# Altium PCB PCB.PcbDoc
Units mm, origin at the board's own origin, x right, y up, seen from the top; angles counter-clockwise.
Board outline 41 x 25.36 mm, 2 copper layers (TOP, BOTTOM), stack 1.586 mm thick; 36 components, 21 nets, 107 pads, 50 vias.
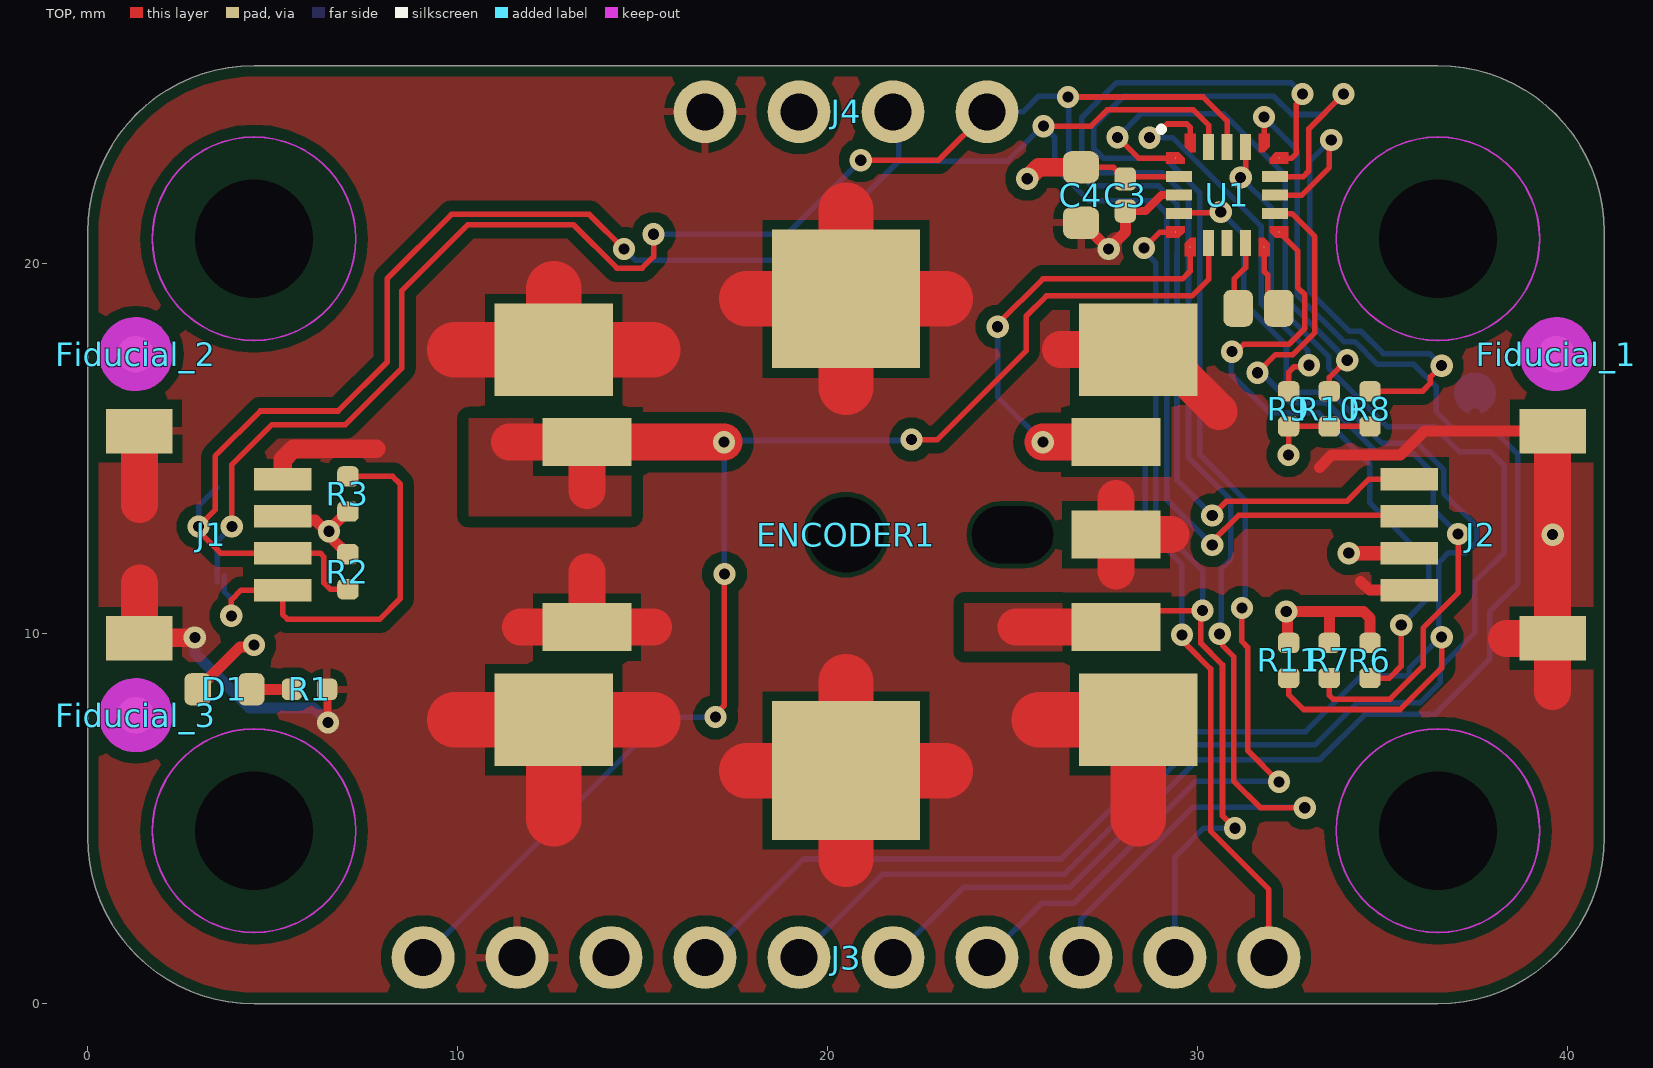
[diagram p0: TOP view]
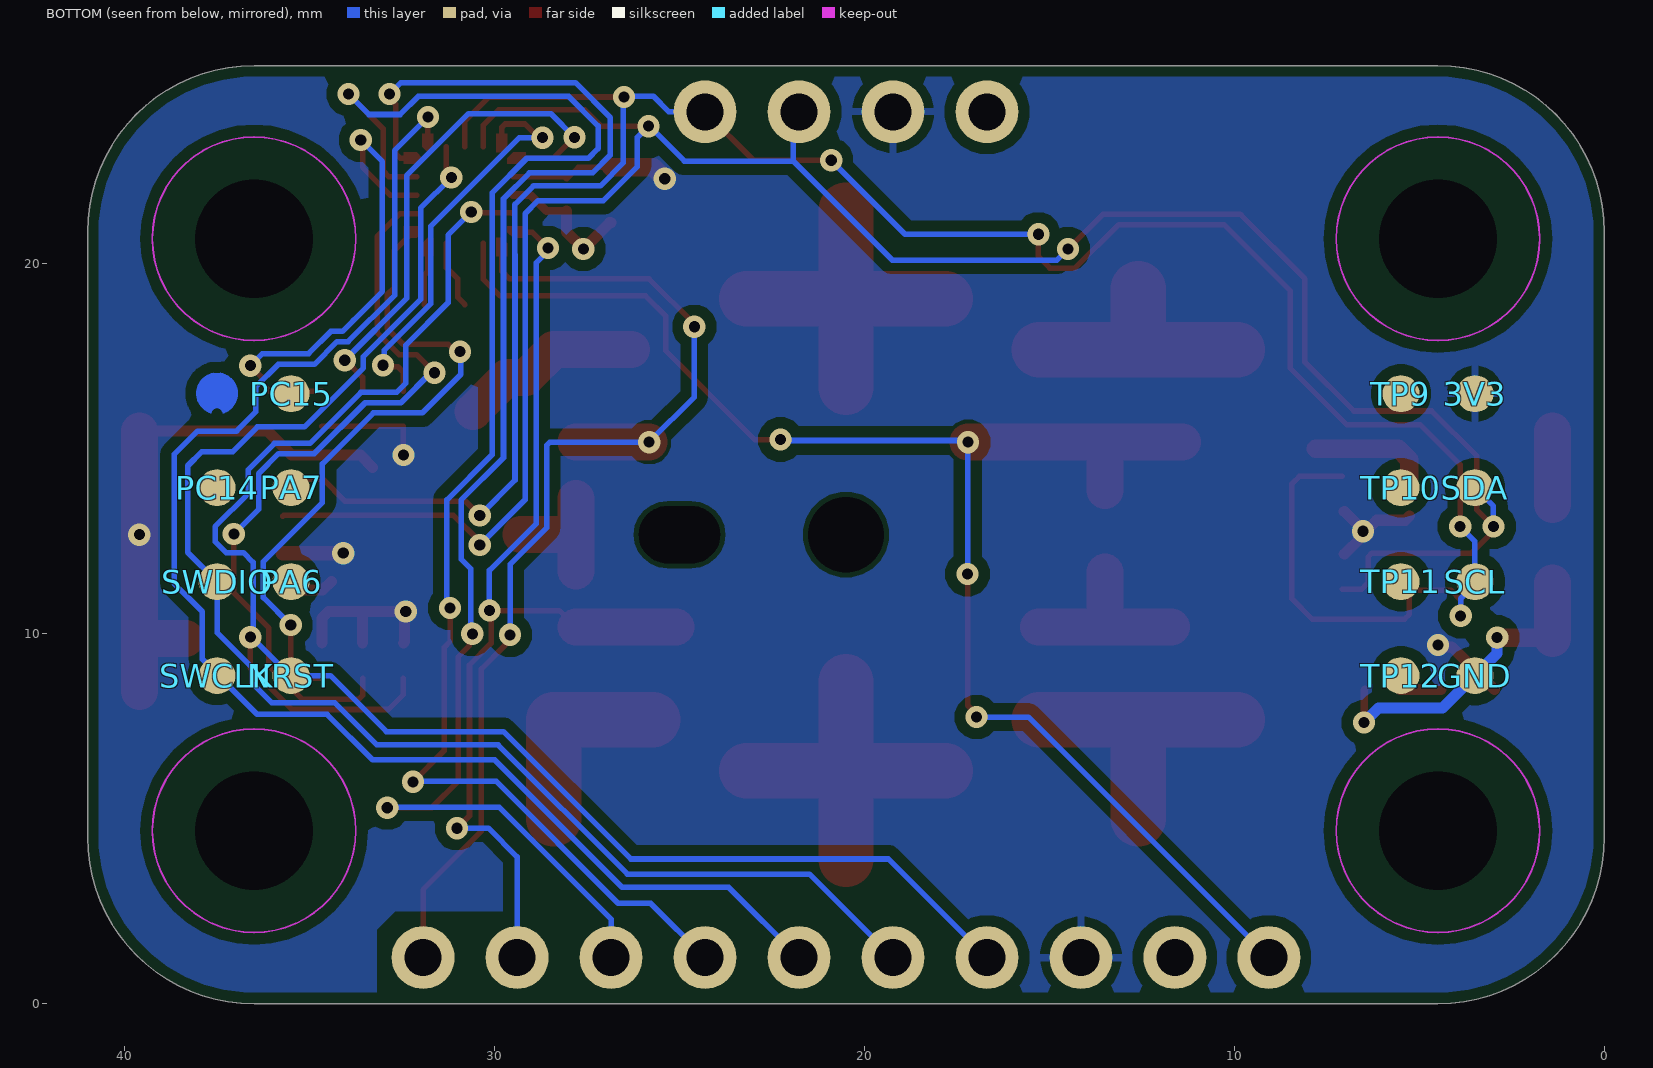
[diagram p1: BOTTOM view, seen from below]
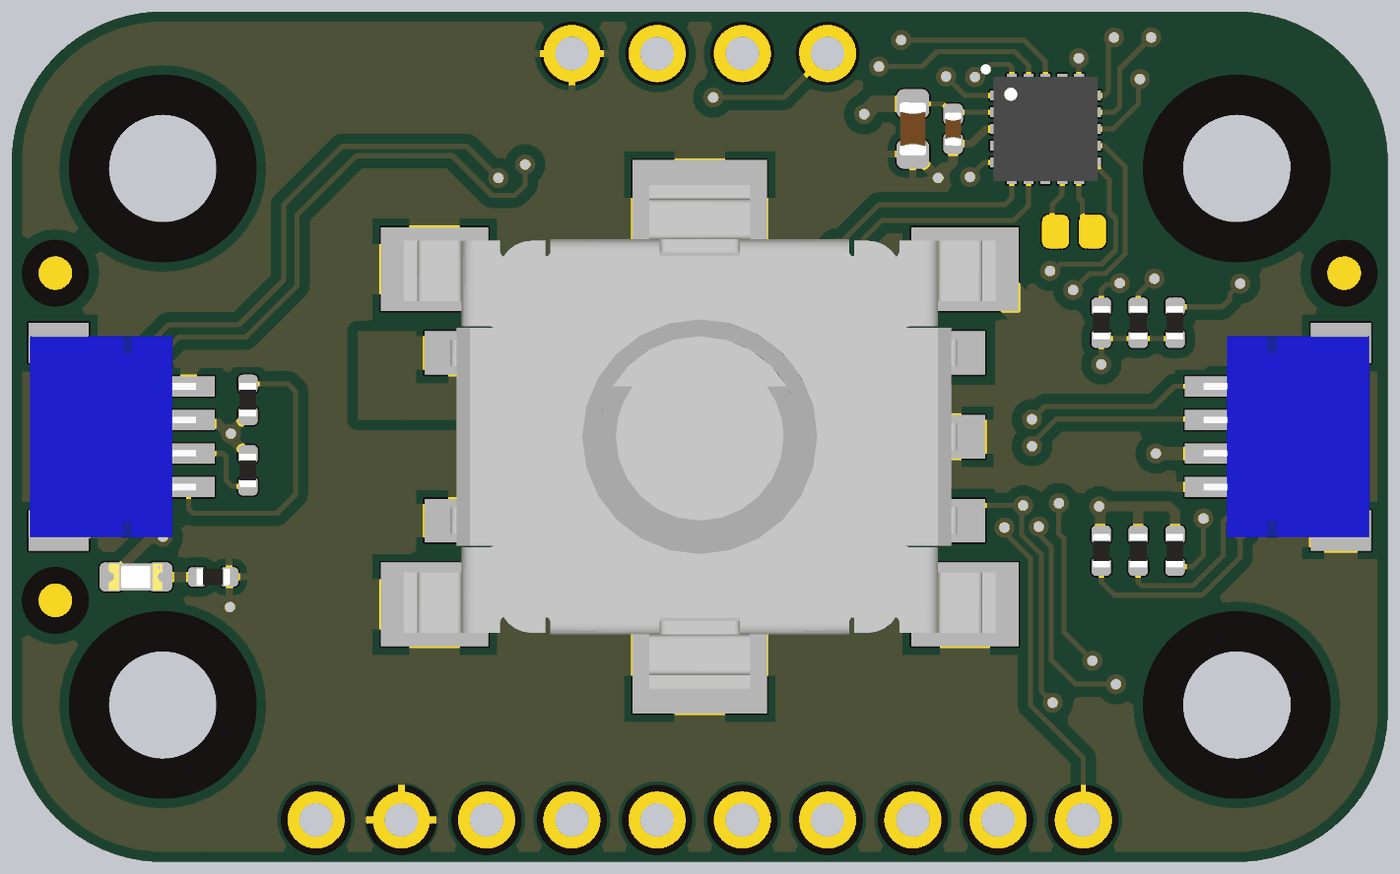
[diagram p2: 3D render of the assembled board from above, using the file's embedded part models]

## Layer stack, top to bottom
Top Solder: solder mask 0.01, Solder Resist, Dk 3.5
TOP: signal copper 0.018
Dielectric: core 1.55, FR-4, Dk 4.8
BOTTOM: signal copper 0.018
Bottom Solder: solder mask 0.01, Solder Resist, Dk 3.5

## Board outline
0,4.5 ccw(c4.5,4.5) 4.5,0 36.5,0 ccw(c36.5,4.5) 41,4.5 41,20.86 ccw(c36.5,20.86) 36.5,25.36 4.5,25.36 ccw(c4.5,20.86) 0,20.86

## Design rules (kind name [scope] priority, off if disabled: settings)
BoardOutlineClearance Version [(ObjectKind = 'Text') And (StringText = '.Version')] p1: gap=0 ignorepadtopadclearanceinfootprint=FALSE
BoardOutlineClearance Mousebites [(ObjectKind = 'Pad') And (Name = 'Free-MOUSEBITE')] p2: gap=0 ignorepadtopadclearanceinfootprint=FALSE
BoardOutlineClearance Silks [(OnLayer('Top Overlay') OR OnLayer('Bottom Overlay'))] p3: gap=0 ignorepadtopadclearanceinfootprint=FALSE
BoardOutlineClearance [All] p4: gap=0.3 ignorepadtopadclearanceinfootprint=FALSE
Clearance COPPER_0.3mm [All] p1: gap=0.127 ignorepadtopadclearanceinfootprint=FALSE except(0.3: Arc-Fill Arc-Poly Arc-Region Track-Fill Track-Poly Track-Region SMDPad-Fill SMDPad-Poly SMDPad-Region THPad-Fill THPad-Poly THPad-Region Via-Fill Via-Poly Via-Region Fill-Fill Fill-Poly Fill-Region Poly-Poly Poly-Region Region-Region)
Clearance "Generic clearance 0.15mm" [All] p2: gap=0.15 ignorepadtopadclearanceinfootprint=FALSE
ComponentClearance [All] p1: gap=0.2 collisioncheckmode=3 verticalgap=0 showdistances=TRUE
DiffPairsRouting USB [InDifferentialPairClass('USB')] p1: maxlimit=0.15 minlimit=0.15 mostfreqgap=0.15 toplayer_minwidth=0.15 toplayer_maxwidth=0.21 toplayer_prefwidth=0.2 bottomlayer_minwidth=0.15 bottomlayer_maxwidth=0.21 bottomlayer_prefwidth=0.2 impedanceprofiledriven=TRUE impedanceprofileid={E6B00C31-4C8E-439C-824F-D2B2CDC26F9C} impedanceprofilevalue=90.000000 maxuncoupledlength=12.7
Height [All] p1: minheight=0 maxheight=30 prefheight=12.7
HoleSize [All] p1: absolutevalues=TRUE maxlimit=30 minlimit=0.3 maxpercent=80.000 minpercent=20.000
HoleToHoleClearance [All] p1: gap=0.25 allowstackedmicrovias=FALSE
MinimumAnnularRing [All] p1: minimumring=0.15
PlaneConnect [All] p1: pad.planeconnectstyle=Relief pad.reliefexpansion=0.508 pad.reliefentries=4 pad.reliefconductorwidth=0.254 pad.reliefairgap=0.254 via.planeconnectstyle=Direct via.reliefexpansion=0.508 via.reliefentries=4 via.reliefconductorwidth=0.254 via.reliefairgap=0.254
PolygonConnect [All] p1: thpad.connectstyle=Relief thpad.reliefconductorwidth=0.2 thpad.reliefentries=4 thpad.polygonreliefangle="90 Angle" thpad.airgapwidth=0.254 smdpad.connectstyle=Relief smdpad.reliefconductorwidth=0.2 smdpad.reliefentries=4 smdpad.polygonreliefangle="90 Angle" smdpad.airgapwidth=0.254 via.connectstyle=Direct via.reliefconductorwidth=0.254 via.reliefentries=4 via.polygonreliefangle="90 Angle" via.airgapwidth=0.254
RoomDefinition TOP [InComponentClass('TOP')] p1: confinementstyle=ConfineIn formatcopy=TRUE lockcomponents=FALSE outline 42.8,3.6 51.5,3.6 51.5,18.3 42.8,18.3
RoutingVias StandardVias [All] p1: holewidth=0.3 width=0.6 viastyle="Through Hole" minholewidth=0.3 minwidth=0.6 maxholewidth=0.3 maxwidth=0.6
SMDToCorner [All] p1: distance=39370
SilkToSilkClearance [All] p1: silktosilkclearance=0.2
SilkToSolderMaskClearance [IsPad] p1: minsilkscreentomaskgap=0.15 clearancetoexposedcopper=TRUE
SolderMaskExpansion VIAtented [IsVia] p1: expansion=0.102 istentingtop=TRUE
SolderMaskExpansion [All] p2: expansion=0.05 istentingtop=FALSE
UnConnectedPin [All] p1:
UnRoutedNet [not WithinRoom('K36')] p1: checkbadconnections=TRUE
ViasUnderSMD [All] p1: allowed=FALSE
Width StandardTraces [All] p1: maxlimit=5 minlimit=0.15 preferedwidth=0.15 minimp=50.000000 maximp=50.000000 favimp=50.000000
21 further rules are at their usual default settings.

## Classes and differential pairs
component class TOP: 3V3 D1 ENCODER1 Fiducial_1 Fiducial_2 Fiducial_3 GND J1 J2 J3 J4 NRST PA6 PA7 PC14 PC15 R1 SCL SDA SWCLK SWDIO TP9 TP10 TP11 TP12
component class U_MICROCONTROLLER: C3 C4 R2 R3 R6 R7 R8 R9 R10 R11 U1

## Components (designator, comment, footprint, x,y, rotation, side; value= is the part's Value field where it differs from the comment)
3V3 "Test point 1.00mm" TP-1.00MM 3.5,16.49 r90 bottom
C3 "0402B104K160CT" CAP-0402 28.05,21.86 r270 top value=100nF
C4 "GRM188R61C475KAAJD" CAP-0603 26.85,21.86 r90 top value=4.7µF
D1 "HSMG-C190" LEDC1608X80N-AK 3.7,8.5 r180 top
ENCODER1 "PEC11J-9215F-S0015" PEC11J-9215F-S0015 20.5,12.68 r90 top
Fiducial_1 "Fiducial mark 1mm" "Fiducial mark 1mm-Footprint-1" 39.7,17.56 r270 top
Fiducial_2 "Fiducial mark 1mm" "Fiducial mark 1mm-Footprint-1" 1.3,17.56 r270 top
Fiducial_3 "Fiducial mark 1mm" "Fiducial mark 1mm-Footprint-1" 1.3,7.8 r270 top
GND "Test point 1.00mm" TP-1.00MM 3.5,8.87 r90 bottom
J1 "SM04B-SRSS-TB(LF)(SN)" SM04B-SRSS-TB(LF)(SN)-Footprint-1 3.337,12.68 r90 top locked
J2 "SM04B-SRSS-TB(LF)(SN)" SM04B-SRSS-TB(LF)(SN)-Footprint-1 37.663,12.68 r270 top locked
J3 "HEADER TH 2.54mm VERT. 1x010POS" "PIN HEADER 2.54mm VERT. 1x10POS" 20.5,1.25 r0 top
J4 "HEADER TH 2.54mm VERT. 1x004POS" "PIN HEADER 2.54mm VERT. 1x4POS-Footprint-1" 20.5,24.11 r0 top
NRST "Test point 1.00mm" TP-1.00MM 35.5,8.87 r180 bottom
PA6 "Test point 1.00mm" TP-1.00MM 35.5,11.41 r180 bottom
PA7 "Test point 1.00mm" TP-1.00MM 35.5,13.95 r180 bottom
PC14 "Test point 1.00mm" TP-1.00MM 37.5,13.95 r180 bottom
PC15 "Test point 1.00mm" TP-1.00MM 35.5,16.49 r180 bottom
R1 "CRCW04021K00FKEDC" RES-0402 6,8.5 r180 top value=1k
R2 "RC0402FR-074K7L" RES-0402 7.039,11.68 r90 top value=4.7k
R3 "RC0402FR-074K7L" RES-0402 7.039,13.78 r270 top value=4.7k
R6 "RC0402FR-074K7L" RES-0402 34.663,9.28 r270 top value=4.7k
R7 "RC0402FR-074K7L" RES-0402 33.563,9.28 r270 top value=4.7k
R8 "RC0402FR-074K7L" RES-0402 34.663,16.08 r90 top value=4.7k
R9 "RC0402FR-074K7L" RES-0402 32.463,16.08 r90 top value=4.7k
R10 "RC0402FR-074K7L" RES-0402 33.563,16.08 r90 top value=4.7k
R11 "RC0402FR-074K7L" RES-0402 32.463,9.28 r270 top value=4.7k
SCL "Test point 1.00mm" TP-1.00MM 3.5,11.41 r90 bottom
SDA "Test point 1.00mm" TP-1.00MM 3.5,13.95 r90 bottom
SWCLK "Test point 1.00mm" TP-1.00MM 37.5,8.87 r180 bottom
SWDIO "Test point 1.00mm" TP-1.00MM 37.5,11.41 r180 bottom
TP9 "Test point 1.00mm" TP-1.00MM 5.5,16.49 r0 bottom
TP10 "Test point 1.00mm" TP-1.00MM 5.5,13.95 r0 bottom
TP11 "Test point 1.00mm" TP-1.00MM 5.5,11.41 r0 bottom
TP12 "Test point 1.00mm" TP-1.00MM 5.5,8.87 r0 bottom
U1 "STM32C011F4U6TR" UFQFPN20 30.8,21.86 r0 top

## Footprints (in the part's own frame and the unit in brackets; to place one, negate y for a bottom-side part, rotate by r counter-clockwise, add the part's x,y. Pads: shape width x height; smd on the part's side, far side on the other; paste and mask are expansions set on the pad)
CAP-0402 [mm] "Chip Capacitor, 2-Leads, Body  0402 (in) 1005 (mm), IPC Medium Density"
  rrect52% 0.63x0.58 smd mask+0.05: 1(-0.435,0) 2(0.435,0)
  body extent -0.5,-0.25 0.5,0.25, height 0.5
CAP-0603 [mm] "Chip Capacitor, Body 0603 imperial,1.6x0.8mm, IPC High Density"
  rrect51% 0.87x0.97 smd mask+0.05: 1(-0.75,0) 2(0.75,0)
  body extent -0.8,-0.4 0.8,0.4, height 0.8
"Fiducial mark 1mm-Footprint-1" [mm]
  round 1 smd paste-10 mask+0.5: 1(0,0)
  TOP keep-out circle w1: c0,0 r0.5
LEDC1608X80N-AK [mm]
  rrect50% 0.72x0.87 smd: A(0.725,0) C(-0.725,0)
  body extent -0.8,-0.4 0.8,0.4, height 0.79
PEC11J-9215F-S0015 [mm]
  rect 1.3x2.4 smd: A(-2.5,-7.3) B(2.5,-7.3) C(0,-7.3) D(-2.5,7) E(2.5,7)
  rect 3.75x4 smd: FIXING(-6.375,0) FIXING(6.375,0)
  rect 2.5x3.2 smd: FIXING(-5,7.9) FIXING(-5,-7.9) FIXING(5,7.9) FIXING(5,-7.9)
  round 0.5 hole 2.05 unplated: PLASTIC(0,0)
  round 0.5 hole 1.55 slot 2.2 at 90 deg unplated: PLASTIC(0,-4.5)
  body extent -7.51,-8.82 7.51,8.82, height 19.52
"PIN HEADER 2.54mm VERT. 1x4POS-Footprint-1" [mm]
  round 1.7 hole 1 mask+0.1: 1(-3.81,0) 2(-1.27,0) 3(1.27,0) 4(3.81,0)
"PIN HEADER 2.54mm VERT. 1x10POS" [mm]
  round 1.7 hole 1 mask+0.2: 1(-11.43,0) 2(-8.89,0) 3(-6.35,0) 4(-3.81,0) 5(-1.27,0) 6(1.27,0) 7(3.81,0) 8(6.35,0) 9(8.89,0) 10(11.43,0)
RES-0402 [mm] "Chip Resistor, 2-Leads, Body  0402 (in) 1005 (mm), IPC Medium Density"
  rrect51% 0.55x0.58 smd mask+0.05: 1(-0.475,0) 2(0.475,0)
  body extent -0.5,-0.25 0.5,0.25, height 0.34
SM04B-SRSS-TB(LF)(SN)-Footprint-1 [mm]
  rect 0.6x1.55 smd mask+0.05: 1(1.5,-1.937) 2(0.5,-1.937) 3(-0.5,-1.937) 4(-1.5,-1.937)
  rect 1.2x1.8 smd mask+0.05: FIX(-2.8,1.938) FIX(2.8,1.938)
  body extent -3,-2.16 3,2.8, height 2.98
TP-1.00MM [mm]
  rrect100% 1x1 smd paste-2.54: X(0,0)
UFQFPN20 [mm] "QFN, 20-Leads, Body 3.00x3.00mm, Pitch 0.50mm, IPC Medium Density"
  round 0.025 smd mask+0.05: 1(-1.4,1) 5(-1.4,-1) 6(-1,-1.4) 10(1,-1.4) 11(1.4,-1) 15(1.4,1) 16(1,1.4) 20(-1,1.4)
  rect 0.7x0.3 smd mask+0.05: 2(-1.3,0.5) 3(-1.3,0) 4(-1.3,-0.5) 12(1.3,-0.5) 13(1.3,0) 14(1.3,0.5)
  rect 0.3x0.7 smd mask+0.05: 7(-0.5,-1.3) 8(0,-1.3) 9(0.5,-1.3) 17(0.5,1.3) 18(0,1.3) 19(-0.5,1.3)
  TOP region: -1.3,-1.15 -1.15,-1 -1.15,-0.85 -1.65,-0.85 -1.65,-1.15
  TOP region: -0.85,-1.65 -1.15,-1.65 -1.15,-1.3 -1,-1.15 -0.85,-1.15
  TOP region: 1.15,-1.65 0.85,-1.65 0.85,-1.15 1,-1.15 1.15,-1.3
  TOP region: 1.65,1.15 1.65,0.85 1.15,0.85 1.15,1 1.3,1.15
  TOP region: 1,1.15 0.85,1.15 0.85,1.65 1.15,1.65 1.15,1.3
  TOP region: -1.15,1 -1.15,0.85 -1.65,0.85 -1.65,1.15 -1.3,1.15
  TOP region: -1.15,1.3 -1,1.15 -0.85,1.15 -0.85,1.65 -1.15,1.65
  TOP region: 1.65,-0.85 1.65,-1.15 1.3,-1.15 1.15,-1 1.15,-0.85
  silkscreen extent -1.8,1.75 -1.75,1.8, body extent -1.55,-1.55 1.55,1.55, height 0.6

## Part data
3V3 GND NRST PA6 PA7 PC14 PC15 SCL SDA SWCLK SWDIO TP9 TP10 TP11 TP12: library part UT0013-A.6, Manufacturer="This is not a component"
C3: library part C0012-A.15, "CAP CHIP 0402 100nF 10% 16V X7R", Case Code (Imperial)=0402, Dielectric=X7R, Manufacturer=Walsin, Tolerance=10%, Voltage=16V
C4: library part C0054-A.16, "CAP CHIP 0603 4.7uF 10% 16V X5R", Case Code (Imperial)=0603, Dielectric=X5R, Manufacturer=Murata, Manufacturer 3="Samsung Electro-Mechanics", Part number 2=GRM188R61C475KE11D, Part number 3=CL10A475KO8NNNC, Tolerance=10%, Voltage=16V
D1: library part L0009-A.5, "LED SMD 0603 GREEN/568 15mcd 120^", Manufacturer=Broadcom
ENCODER1: library part S0054-A.2, "ENCODER 2b quadrature, 15PPR, 30 detents, shaft 15mm D-Cut, switch 350+-100gf, SMD 15x18x20mm", Manufacturer=Bourns
Fiducial_1 Fiducial_2 Fiducial_3: library part UT0023-A.7, "Fiducial mark 1mm clearance 2mm"
J1 J2: library part J0005-A.2, "CONN JST 4POS SIDE 1MM TIN QWIIC", Manufacturer=JST
J3: library part J0169-A.8
J4: library part J0162-A.5
R1: library part R0007-A.24, "RES CHIP 0402 1k 1% 1/16W", Case Code (Imperial)=0402, Manufacturer=Vishay, Power=62.5mW, Temperature Coefficient=100ppm, Tolerance=1%
R2 R3 R6 R7 R8 R9 R10 R11: library part R0013-A.24, "RES CHIP 0402 4k7 1% 1/16W", Case Code (Imperial)=0402, Manufacturer=YAGEO, Power=62.5mW, Temperature Coefficient=200ppm, Tolerance=1%
U1: library part U0363-A.3, "IC Cortex M0, 32b MCU, 32KB Flash, 6KB RAM, VDD 2-3.6V, -40°C to 85°C, QFN20 3x3mm", Manufacturer="ST Microelectronics"

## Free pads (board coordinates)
  rrect50% 0.8x1 smd paste-2539.97: 3V10(31.1,18.8) 3V10(32.2,18.8)
  round 3 hole 3.2 unplated paste-2539.97 mask+1.3: MH(4.5,4.68) MH(4.5,20.68) MH(36.5,4.68) MH(36.5,20.68)

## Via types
v1: diameter 0.6, hole 0.3, TOP to BOTTOM, tented both sides, 50 vias

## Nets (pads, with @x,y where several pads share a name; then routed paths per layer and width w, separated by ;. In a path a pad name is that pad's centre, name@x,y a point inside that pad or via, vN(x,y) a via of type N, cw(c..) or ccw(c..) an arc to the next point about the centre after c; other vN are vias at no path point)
+3V3: 3V3.X C3.1 C4.2 D1.A J1.2 J2.2 J3.3 J4.2 R2.2 R3.2 R6.1 R7.1 R8.1 R9.1 R10.1 R11.1 U1.2 | length 18.8
  TOP w0.15: C4.2 27.735,22.61 C3.1 28.115,22.36 U1.2 ; v1(32.463,14.837) R9.1 R10.1 R8.1
  TOP w0.3: D1.A 4.118,9.643 4.443,9.643 v1(4.5,9.7) ; J1.2 5.384,13.07 6.154,13.07 6.453,12.772 v1(6.53,12.772) ; R2.2 7.024,12.155 6.587,12.592 6.587,12.714 v1(6.53,12.772) ; R3.2 7.024,13.305 6.608,12.889 6.608,12.85 v1(6.53,12.772) ; R11.1 32.432,9.787 32.432,10.568 v1(32.4,10.6) 34.487,10.6 34.663,10.424 R6.1 ; 33.514,10.6 33.563,10.551 R7.1
  TOP w0.4: v1(34.088,12.18) J2.2
  TOP w0.5: v1(25.4,22.3) 25.71,22.61 C4.2
GND: C3.2 C4.1 ENCODER1.C ENCODER1.D ENCODER1.FIXING GND.X J1.1 J1.FIX J2.1 J2.FIX J3.2 J4.1 R1.1 U1.3 | length 88.4
  TOP w0.2: R1.1 6.488,8.488 6.488,7.612 v1(6.5,7.6)
  TOP w0.22: C3.2 28.592,21.425 29.027,21.86 U1.3
  TOP w0.3: C4.1 26.895,21.11 v1@27.6,20.405 ; v1(27.6,20.4) v1@27.6,20.405 ; C3.2 28.05,20.866 27.6,20.416 v1@27.6,20.405 ; 33.3,14.5 33.628,14.828 35.486,14.828 36.138,15.48 J2.FIX@39.601,15.48 ; 34.406,11.419 34.645,11.18 J2.1
  TOP w0.5: J1.FIX@1.399,9.88 1.419,9.9 v1(2.9,9.9) ; J1.1 5.275,14.707 5.567,15 7.8,15
  TOP w1: J1.FIX@1.399,9.88 1.399,11.379 ; 1.399,13.499 J1.FIX@1.399,15.48 ; 11.7,10.18 ENCODER1.D ; 13.5,11.671 ENCODER1.D ; 15.3,10.18 ENCODER1.D ; 26.3,17.68 28.4,17.68 29.15,16.93 29.661,16.93 30.581,16.01 ; 27.8,11.7 ENCODER1.C ; 27.8,13.66 ENCODER1.C ; 29.291,12.68 ENCODER1.C ; 38.353,9.88 J2.FIX@39.601,9.88 ; 39.601,8.443 J2.FIX@39.601,9.88 ; J2.FIX@39.601,15.48 J2.FIX@39.601,9.88
  TOP w1.5: 9.92,7.68 ENCODER1.FIXING@12.6,7.68 ; 9.92,17.68 12.6,17.68 15.28,17.68 ; ENCODER1.FIXING@12.594,17.686 12.594,19.328 ; 12.6,5 ENCODER1.FIXING@12.6,7.68 ; 15.28,7.68 ENCODER1.FIXING@12.6,7.68 ; 17.82,6.305 ENCODER1.FIXING@20.5,6.305 ; 17.82,19.055 ENCODER1.FIXING@20.5,19.055 ; 20.5,3.91 ENCODER1.FIXING@20.5,6.305 ; 20.5,8.7 ENCODER1.FIXING@20.5,6.305 ; 20.5,16.66 ENCODER1.FIXING@20.5,19.055 ; 20.5,21.45 ENCODER1.FIXING@20.5,19.055 ; 23.18,6.305 ENCODER1.FIXING@20.5,6.305 ; 23.18,19.055 ENCODER1.FIXING@20.5,19.055 ; 25.72,7.68 28.4,7.68 28.4,5
  BOTTOM w0.3: v1(2.9,9.9) 2.9,9.47 GND.X 4.372,7.998 6.102,7.998 v1(6.5,7.6)
  other v1: 39.601,12.68
NetD1_C: D1.C R1.2 | length 1.1
  TOP w0.3: D1.C R1.2
NetU1_8: U1.8
NetU1_9: pad.3V10@31.1,18.8 U1.9 | length 1.9
  TOP w0.15: pad.3V10@30.8,18.9 31,19.1 31,19.6 31.3,19.9 U1.9
NetU1_10: pad.3V10@32.2,18.8 U1.10 | length 1.6
  TOP w0.15: U1.10 31.8,19.8 31.9,19.7 pad.3V10@31.9,18.9
PA0_1: ENCODER1.A J3.9 U1.5 | length 27.7
  TOP w0.15: ENCODER1.A 28.249,10.629 v1(30.137,10.629) 30.091,10.583 30.091,9.745 30.677,9.159 30.677,5.083 v1(31.014,4.746) ; v1(28.552,20.428) 28.984,20.86 U1.5
  TOP w1: 25.1,10.18 ENCODER1.A
  BOTTOM w0.15: v1(28.552,20.428) 28.552,20.353 28.87,20.035 28.87,12.98 30.137,11.713 v1(30.137,10.629) ; J3.9 29.39,3.97 30.166,4.746 v1(31.014,4.746)
PA1_1: ENCODER1.B J3.10 U1.6 | length 30.2
  TOP w0.15: v1(24.6,18.3) 24.6,18.372 25.823,19.595 29.595,19.595 29.8,19.8 U1.6 ; v1(29.579,9.973) 29.579,9.851 29.727,9.703 29.727,9.678 30.353,9.051 30.353,4.667 31.93,3.09 J3.10
  TOP w1: v1(25.82,15.18) ENCODER1.B
  BOTTOM w0.15: v1(24.6,18.3) 24.6,16.4 v1(25.82,15.18) 28.505,15.18 28.593,15.092 28.593,12.866 29.579,11.88 v1(29.579,9.973)
PA2_1: ENCODER1.E J3.1 U1.7 | length 41.7
  TOP w0.15: v1(16.97,7.75) 16.97,7.823 17.21,8.063 v1@17.21,11.613 ; v1(22.27,15.25) 22.97,15.25 25.37,17.65 25.37,18.584 25.918,19.132 29.852,19.132 30.3,19.58 U1.7
  TOP w1: 11.4,15.18 ENCODER1.E ; 13.5,13.88 ENCODER1.E ; v1(17.2,15.18) ENCODER1.E
  BOTTOM w0.15: J3.1 15.57,7.75 v1(16.97,7.75) ; v1(17.216,11.619) 17.208,11.627 17.208,15.172 v1(17.2,15.18) 17.245,15.225 22.245,15.225 v1(22.27,15.25)
PA6_2: R6.2 U1.11 | length 17.9
  TOP w0.15: v1(30.937,17.626) 31.053,17.626 31.249,17.823 32.466,17.823 32.899,18.255 32.899,19.17 32.705,19.364 32.705,20.355 U1.11 ; R6.2 35.184,8.805 35.508,9.128 v1(35.508,10.241)
  BOTTOM w0.15: v1(30.937,17.626) 30.913,17.602 30.913,17.01 31.953,15.97 33.276,15.97 34.652,14.594 34.652,13.548 36.246,11.954 36.246,10.979 v1(35.508,10.241)
PA7_2: R7.2 U1.12 | length 21.1
  TOP w0.15: v1(31.624,17.056) 32.113,17.546 32.581,17.546 33.176,18.141 33.176,20.734 32.55,21.36 U1.12 ; R7.2 33.563,8.337 33.665,8.234 35.203,8.234 36.098,9.129 36.098,10.158 37.054,11.114 37.054,12.689 v1(37.046,12.697)
  BOTTOM w0.15: v1(31.624,17.056) 31.723,17.056 32.533,16.247 33.495,16.247 34.873,14.869 35.835,14.869 36.378,14.326 36.378,13.365 v1(37.046,12.697)
PA8_2: R8.2 U1.13 | length 13.6
  TOP w0.15: U1.13 32.822,21.86 33.567,22.605 33.567,23.3 v1(33.615,23.347) ; R8.2 36.075,16.555 36.295,16.775 36.295,16.941 v1(36.601,17.247)
  BOTTOM w0.15: v1(33.615,23.347) 33.029,22.762 33.029,19.258 33.816,18.471 34.114,18.173 34.427,18.173 35.027,17.573 36.275,17.573 v1(36.601,17.247)
PA9_USART1_TX_1: J3.7 U1.14 | length 41.7
  TOP w0.15: v1(31.2,10.7) 31.2,10.31 31.198,10.308 31.198,9.794 31.358,9.633 31.358,6.842 v1(32.2,6) ; U1.14 32.86,22.36 33.008,22.508 33.008,23.648 v1(33.95,24.59)
  BOTTOM w0.15: J3.7 25.778,2.718 26.66,2.718 29.952,6.01 32.19,6.01 v1(32.2,6) ; v1(31.2,10.7) 31.286,10.786 31.286,13.622 30.067,14.841 30.067,21.917 29.13,22.854 27.463,22.854 27.199,23.118 27.199,23.73 27.998,24.53 32.058,24.53 32.551,24.037 33.397,24.037 v1(33.95,24.59)
PA10_USART1_RX_1: J3.8 U1.15 | length 40.1
  TOP w0.15: v1(30.6,10) 30.686,9.914 30.686,9.676 30.978,9.384 30.978,6.022 31.7,5.3 v1(32.9,5.3) ; U1.15 32.554,22.86 32.671,22.977 32.671,24.312 32.841,24.482 v1(32.841,24.591)
  BOTTOM w0.15: J3.8 26.85,2.289 29.871,5.31 32.89,5.31 v1(32.9,5.3) ; v1(30.6,10) 30.639,10.039 30.639,11.756 30.902,12.019 30.902,13.614 29.757,14.759 29.757,21.759 29.056,22.46 27.35,22.46 26.871,22.939 26.871,23.956 27.816,24.9 32.531,24.9 v1(32.841,24.591)
PA13_SWDIO_1: J3.6 SWCLK.X U1.16 | length 39.4
  TOP w0.15: v1@31.744,24.019 v1(31.795,23.968) 31.8,23.963 U1.16
  BOTTOM w0.15: J3.6 23.671,3.151 26.553,3.151 29.998,6.596 33.296,6.596 34.523,7.823 36.413,7.823 37.48,8.89 37.48,8.899 37.9,9.319 37.9,10.6 38.662,11.362 38.662,14.848 38.029,15.481 36.974,15.481 36.456,16 36.456,16.672 35.846,17.282 34.869,17.282 34.255,17.896 33.955,17.896 32.702,19.149 32.702,23.061 v1(31.795,23.968)
PA14_SWCLK_BOOT0_1: J3.5 SWDIO.X U1.17 | length 39.8
  TOP w0.15: v1(31.167,22.336) 31.167,22.429 31.3,22.562 U1.17
  BOTTOM w0.15: J3.5 21.487,3.507 26.409,3.507 29.902,7 33.181,7 34.324,8.143 36.027,8.143 36.557,8.673 36.557,9.089 37.5,10.032 SWDIO.X 38.291,12.201 38.291,14.543 37.907,14.927 37.073,14.927 36.408,15.592 35.14,15.592 33.545,17.186 33.545,17.491 31.998,19.038 31.998,21.506 v1(31.167,22.336)
PC14_2: R9.2 U1.20 | length 11.1
  TOP w0.15: v1(28.7,23.41) 28.808,23.41 29.178,23.781 29.712,23.781 29.8,23.693 U1.20 ; R9.2 32.463,17.068 32.614,17.219 32.973,17.219 v1(33.014,17.259)
  BOTTOM w0.15: v1(28.7,23.41) 29.33,23.41 31.721,21.02 31.721,18.924 32.985,17.659 v1@32.985,17.288
PC15_2: R10.2 U1.1 | length 14
  TOP w0.15: v1@27.85,23.42 28.41,22.86 U1.1 ; R10.2 33.563,16.93 34.027,17.394 v1(34.047,17.394)
  BOTTOM w0.15: v1(27.84,23.42) 28.48,24.06 30.698,24.06 32.375,22.383 32.375,19.066 v1(34.047,17.394)
PF2_N\R\S\T\_1: J3.4 NRST.X R11.2 U1.4 | length 47
  TOP w0.15: U1.4 29.52,21.38 30.61,21.38 v1(30.63,21.4) ; R11.2 32.463,8.359 32.866,7.955 35.479,7.955 36.6,9.076 v1(36.6,9.91)
  BOTTOM w0.15: J3.4 19.354,3.914 26.316,3.914 29.761,7.359 32.923,7.359 34.434,8.87 NRST.X 35.722,8.87 35.722,9.062 36.57,9.91 v1(36.6,9.91) 36.523,9.987 36.523,11.932 36.786,12.195 37.254,12.195 37.553,12.493 37.553,12.901 36.655,13.798 36.655,14.27 36.655,14.441 35.95,15.146 34.988,15.146 33.61,16.524 32.647,16.524 32.396,16.776 32.396,17.805 31.252,18.948 31.252,20.778 v1(30.63,21.4)
SCL_1: J1.4 J2.4 J4.4 R3.1 SCL.X U1.18 | length 69.3
  TOP w0.15: v1(3.886,10.486) 3.886,10.916 4.15,11.18 J1.4 5.275,10.525 5.4,10.4 7.9,10.4 8.452,10.952 8.452,14.048 8.245,14.255 R3.1@7.089,14.255 ; v1(3.9,12.9) 3.9,14.573 4.976,15.649 6.963,15.649 8.496,17.182 8.496,19.278 10.28,21.062 13.128,21.062 14.305,19.885 14.988,19.885 15.302,20.199 15.302,20.798 v1(15.3,20.8) ; v1(20.9,22.8) 23,22.8 J4.4 ; v1(26.5,24.51) 30.151,24.51 30.8,23.861 U1.18 ; v1(30.4,13.2) 30.783,13.583 34.041,13.583 34.638,14.18 J2.4
  BOTTOM w0.15: SCL.X 3.5,12.5 v1(3.9,12.9) ; SCL.X@3.694,11.557 3.694,11.14 3.886,10.948 v1(3.886,10.486) ; v1(15.3,20.8) 18.9,20.8 v1(20.9,22.8) ; J4.4 25.288,24.11 25.71,24.532 26.478,24.532 v1(26.5,24.51) 26.516,24.494 26.516,22.735 27.141,22.11 28.947,22.11 29.452,21.605 29.452,20.245 29.447,20.24 29.447,14.153 v1(30.4,13.2)
SDA_1: J1.3 J2.3 J4.3 R2.1 SDA.X U1.19 | length 63.8
  TOP w0.15: R2.1@7.089,11.205 6.564,11.205 6.49,11.28 6.389,11.38 6.389,12.08 6.289,12.18 J1.3 3.598,12.18 3.186,12.592 3,12.778 v1(3,12.9) 3.448,13.348 3.448,14.801 4.67,16.022 6.772,16.022 8.1,17.351 8.1,19.601 9.838,21.339 13.561,21.339 v1(14.5,20.4) ; v1(25.838,23.722) 27.122,23.722 27.56,24.16 29.888,24.16 30.3,23.748 U1.19 ; v1(30.4,12.4) 30.4,12.49 31.12,13.21 35.696,13.21 J2.3
  BOTTOM w0.15: v1(3,12.9) 3,13.45 SDA.X ; v1(14.5,20.4) 14.8,20.1 19.25,20.1 21.926,22.776 ; J4.3 21.926,23.954 21.926,22.776 ; v1(30.4,12.4) 29.17,13.63 29.17,21.359 28.819,21.71 27.058,21.71 26.138,22.629 26.138,23.422 v1(25.838,23.722) 25.814,23.722 24.869,22.776 21.926,22.776
pads on no net: ENCODER1.PLASTIC Fiducial_1.1 Fiducial_2.1 Fiducial_3.1 PA6.X PA7.X PC14.X PC15.X TP9.X TP10.X TP11.X TP12.X

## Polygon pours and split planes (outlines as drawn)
GND on TOP "NONET_L04_P-001" (solid, remove dead copper, pour order 6): 0,4.5 ccw(c4.5,4.5) 4.5,0 36.5,0 ccw(c36.5,4.5) 41,4.5 41,20.86 ccw(c36.5,20.86) 36.5,25.36 4.5,25.36 ccw(c4.5,20.86) 0,20.86
PA0_1 on TOP "NONET_L04_P-001" (solid, remove dead copper, pour order 0): 29,10.83 29,9.53 23.7,9.53 23.7,10.83
PA2_1 on TOP "NONET_L04_P-001" (solid, remove dead copper, pour order 1): 14.7,15.83 14.7,13.18 10.3,13.18 10.3,15.83
GND on TOP "NONET_L04_P-001" (solid, remove dead copper, pour order 2): 0,25.36 0,0 3.2,0 3.2,25.36
GND on TOP "NONET_L04_P-001" (solid, remove dead copper, pour order 5): 41,25.36 41,0 37.8,0 37.8,25.36
+3V3 on BOTTOM "NONET_L04_P-001" (solid, remove dead copper, pour order 3): 0,4.5 ccw(c4.5,4.5) 4.5,0 36.5,0 ccw(c36.5,4.5) 41,4.5 41,20.86 ccw(c36.5,20.86) 36.5,25.36 4.5,25.36 ccw(c4.5,20.86) 0,20.86
GND on BOTTOM "NONET_L04_P-001" (solid, remove dead copper, pour order 4): 41,25.36 41,0 33.181,0 33.181,2 32.681,2.5 29.6,2.5 29.6,25.36

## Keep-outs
Keep-Out Layer:
  circle w0.05: c36.5,4.68 r2.75
  circle w0.05: c36.5,20.68 r2.75
  circle w0.05: c4.5,4.68 r2.75
  circle w0.05: c4.5,20.68 r2.75

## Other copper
BOTTOM:
  region: 441 vertices and 0 holes, not listed, extent 36.945,15.962 38.056,17.054

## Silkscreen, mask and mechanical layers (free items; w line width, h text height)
Route Tool Path:
  lines w2: -1,8.498 -1,16.86 ; 42,4.5 cw(c36.5,4.5) 36.5,-1 ; 42,8.498 42,16.86 ; -1,4.498 cw(c0,4.5) -1,4.5 ccw(c4.5,4.5) -1,4.498 ; -1,4.498 ccw(c4.5,4.5) 4.498,-1 ; -1,20.86 cw(c4.5,20.86) 4.5,26.36 ; -1,20.86 -1,20.86 ; 4.498,-1 ccw(c4.5,0) 4.5,-1 ; 4.498,-1 ccw(c4.5,4.5) 4.5,-1 ; 4.5,-1 36.5,-1 ; 4.5,26.36 4.5,26.36 ; 4.5,26.36 36.5,26.36 ; 36.5,-1 36.5,-1 ; 36.5,26.36 cw(c36.5,25.36) 36.502,26.36 ; 36.5,26.36 cw(c36.5,20.86) 36.502,26.36 ; 36.502,26.36 cw(c36.5,20.86) 42,20.863 ; 42,20.863 cw(c36.5,20.86) 42,20.86 ccw(c41,20.86) 42,20.863
Mechanical 66:
  circle w0.05: c36.5,4.68 r2.85
  circle w0.05: c36.5,20.68 r2.85
  circle w0.05: c4.5,20.68 r2.85
  circle w0.05: c4.5,4.68 r2.85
